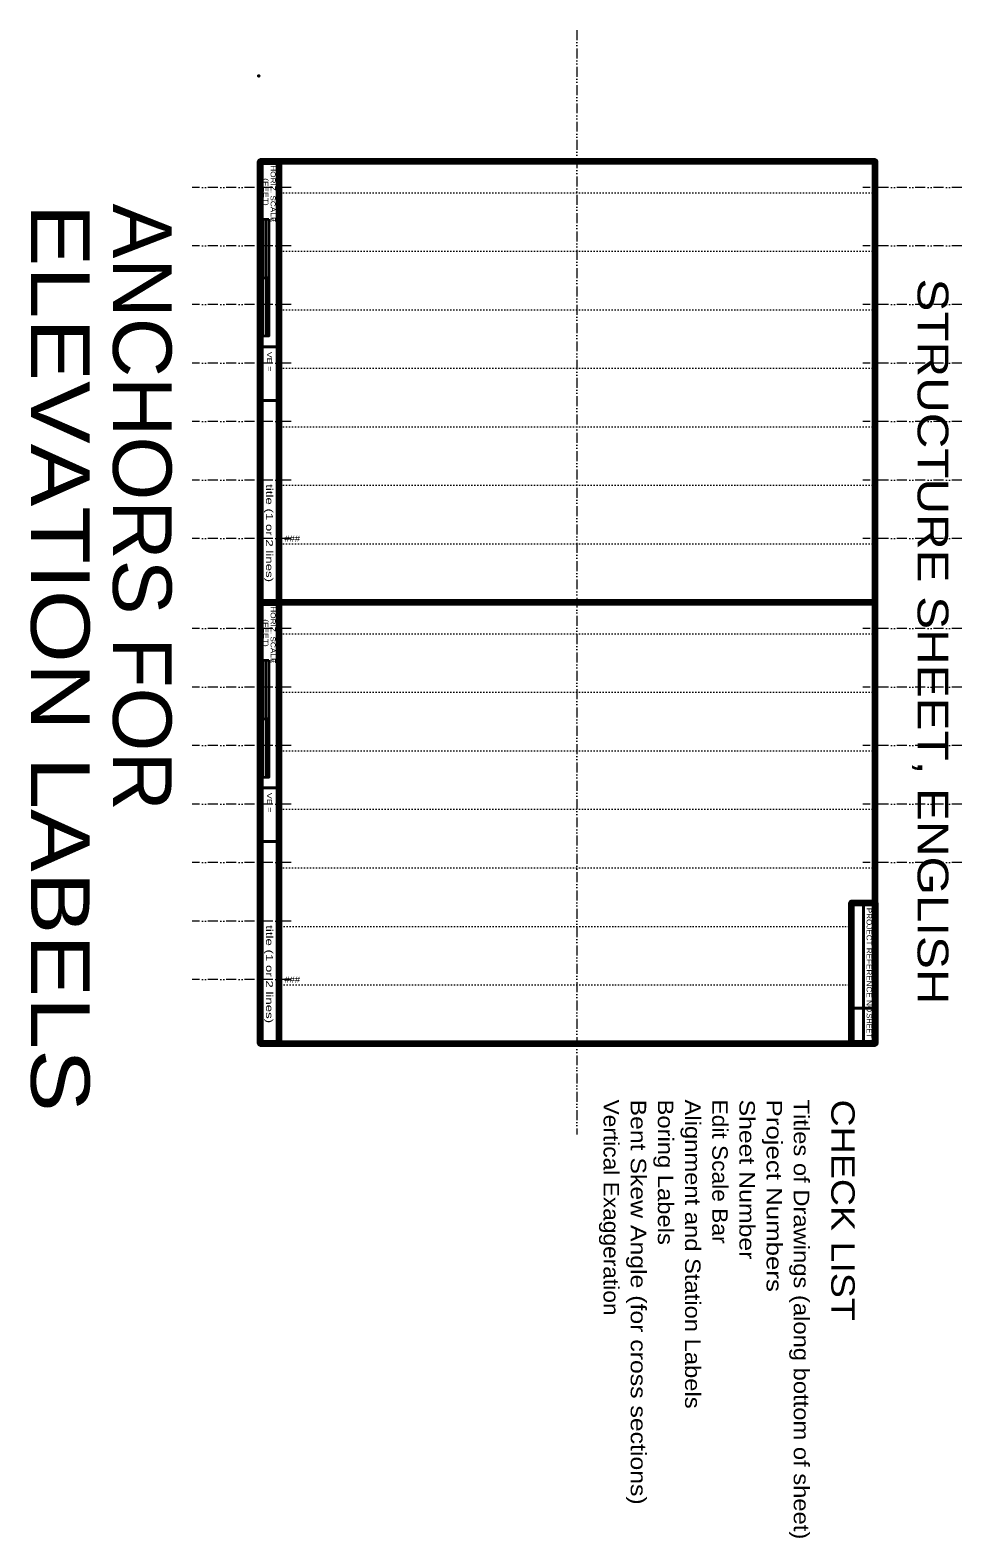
# Model space of a CAD drawing. Extents: x 278712 to 279914, y 171254 to 171792.
# Drawn here: x 279451 to 279610.1, y 171276.1 to 171533.7 of the extents above; entities that cross this region are included whole.
import ezdxf
from ezdxf.enums import TextEntityAlignment as Align

# ---------------------------------------------------------------- set-up
doc = ezdxf.new("R2010")
doc.units = 0
doc.header["$LTSCALE"] = 0.34
doc.header["$PDMODE"] = 32
doc.header["$PDSIZE"] = 0.17
doc.linetypes.add('DASH_DOUBLE_DOT', pattern=[9.2, 5, -1.2, 0.3, -1.2, 0.3, -1.2])
doc.linetypes.add('DOTTED', pattern=[1.5, 0.3, -1.2])
for name, color, linetype, lineweight in [('11', 7, 'DOTTED', 13), ('46', 7, 'DASH_DOUBLE_DOT', 13), ('60', 7, 'Continuous', 35), ('62', 7, 'Continuous', 35)]:
    doc.layers.add(name, color=color, linetype=linetype, lineweight=lineweight)
doc.layers.add('12', color=7, linetype='Continuous')

msp = doc.modelspace()

# ---------------------------------------------------------------- linework, layer by layer
at = {"layer": '11'}
for p, q in [((279595.3064, 171505.949), (279493.5061, 171505.949)), ((279595.3064, 171495.949), (279493.5061, 171495.949)), ((279595.3064, 171485.949), (279493.5061, 171485.949)), ((279595.3064, 171475.949), (279493.5061, 171475.949)), ((279595.3064, 171465.949), (279493.5061, 171465.949)), ((279595.3064, 171455.949), (279493.5061, 171455.949)), ((279595.3064, 171445.949), (279493.5061, 171445.949)), ((279595.3064, 171430.591), (279493.5061, 171430.591)), ((279595.3064, 171420.591), (279493.5061, 171420.591)), ((279595.3064, 171410.591), (279493.5061, 171410.591)), ((279595.3064, 171400.591), (279493.5061, 171400.591)), ((279595.3064, 171390.591), (279493.5061, 171390.591)), ((279591.3064, 171380.591), (279493.5061, 171380.591)), ((279591.3064, 171370.591), (279493.5061, 171370.591))]:
    msp.add_line(p, q, dxfattribs=at)
at = {"layer": '46'}
for p, q in [((279544.4064, 171533.7227), (279544.4064, 171345.0492)), ((279495.5874, 171506.8455), (279478.6921, 171506.8455)), ((279610.1204, 171506.8455), (279593.2251, 171506.8455)), ((279495.5874, 171496.8455), (279478.6921, 171496.8455)), ((279610.1204, 171496.8455), (279593.2251, 171496.8455)), ((279495.5874, 171486.8455), (279478.6921, 171486.8455)), ((279610.1204, 171486.8455), (279593.2251, 171486.8455)), ((279495.5874, 171476.8455), (279478.6921, 171476.8455)), ((279610.1204, 171476.8455), (279593.2251, 171476.8455)), ((279495.5874, 171466.8455), (279478.6921, 171466.8455)), ((279610.1204, 171466.8455), (279593.2251, 171466.8455)), ((279495.5874, 171456.8455), (279478.6921, 171456.8455)), ((279610.1204, 171456.8455), (279593.2251, 171456.8455)), ((279495.5874, 171446.8455), (279478.6921, 171446.8455)), ((279610.1204, 171446.8455), (279593.2251, 171446.8455)), ((279495.5874, 171431.4875), (279478.6921, 171431.4875)), ((279610.1204, 171431.4875), (279593.2251, 171431.4875)), ((279495.5874, 171421.4875), (279478.6921, 171421.4875)), ((279610.1204, 171421.4875), (279593.2251, 171421.4875)), ((279495.5874, 171411.4875), (279478.6921, 171411.4875)), ((279610.1204, 171411.4875), (279593.2251, 171411.4875)), ((279495.5874, 171401.4875), (279478.6921, 171401.4875)), ((279610.1204, 171401.4875), (279593.2251, 171401.4875)), ((279495.5874, 171391.4875), (279478.6921, 171391.4875)), ((279610.1204, 171391.4875), (279593.2251, 171391.4875)), ((279495.5874, 171381.4875), (279478.6921, 171381.4875)), ((279495.5874, 171371.4875), (279478.6921, 171371.4875))]:
    msp.add_line(p, q, dxfattribs=at)
at = {"layer": '60', "lineweight": 40}
for p, q in [((279493.5061, 171479.603), (279490.3061, 171479.6032)), ((279493.5061, 171470.4395), (279490.3061, 171470.4397)), ((279490.3061, 171459.949), (279490.3061, 171435.949)), ((279493.5061, 171404.245), (279490.3061, 171404.245)), ((279493.5061, 171395.0815), (279490.3061, 171395.0815)), ((279490.3061, 171384.591), (279490.3061, 171360.591)), ((279591.3064, 171384.591), (279591.3064, 171360.591)), ((279595.3064, 171384.591), (279591.3064, 171384.591)), ((279593.3064, 171384.591), (279593.3064, 171360.591)), ((279595.3064, 171366.591), (279591.3064, 171366.5912))]:
    msp.add_line(p, q, dxfattribs=at)
at = {"layer": '60', "lineweight": 90}
msp.add_line((279595.3064, 171435.949), (279490.3061, 171435.949), dxfattribs=at)
for points in [[(279493.5064, 171511.307), (279493.5061, 171435.949), (279490.3059, 171435.949), (279490.3061, 171511.307)], [(279490.3061, 171511.307), (279490.3061, 171360.591), (279595.3064, 171360.591), (279595.3064, 171511.307)], [(279493.5064, 171435.949), (279493.5061, 171360.591), (279490.3059, 171360.591), (279490.3061, 171435.949)], [(279595.3064, 171384.591), (279595.3064, 171360.591), (279591.3064, 171360.591), (279591.3064, 171384.591)]]:
    msp.add_lwpolyline(points, close=True, dxfattribs=at)
at = {"layer": '60'}
for points in [[(279491.8201, 171501.4097), (279491.8201, 171481.4097), (279490.8201, 171481.4097), (279490.8201, 171501.4097)], [(279491.8201, 171501.4097), (279491.8201, 171491.4097), (279491.3201, 171491.4097), (279491.3201, 171501.4097)], [(279491.3201, 171491.4097), (279491.3201, 171481.4097), (279490.8201, 171481.4097), (279490.8201, 171491.4097)], [(279491.8201, 171426.0517), (279491.8201, 171406.0517), (279490.8201, 171406.0517), (279490.8201, 171426.0517)], [(279491.8201, 171426.0517), (279491.8201, 171416.0517), (279491.3201, 171416.0517), (279491.3201, 171426.0517)], [(279491.3201, 171416.0517), (279491.3201, 171406.0517), (279490.8201, 171406.0517), (279490.8201, 171416.0517)]]:
    msp.add_lwpolyline(points, close=True, dxfattribs=at)
for p in [(279490.0884, 171525.9155), (279595.5241, 171360.4217)]:
    msp.add_point(p, dxfattribs=at)

# ---------------------------------------------------------------- texts
at = {"layer": '12', "width": 1.2}
for p in [(279495.7869, 171446.3455), (279495.7867, 171370.9875)]:
    msp.add_text('###', height=1, dxfattribs=at).set_placement(p, align=Align.CENTER)
at = {"layer": '60'}
for s, height, width, p in [('HORIZ. SCALE', 0.84, 1.25, (279492.1061, 171505.7641)), ('(FEET)', 0.84, 1.3, (279490.8661, 171506.0783)), ('0', 0.84, 0.9, (279492.2956, 171501.3732)), ('STRUCTURE SHEET, ENGLISH', 5.25, 1.2, (279602.5681, 171429.2638)), ('title (1 or 2 lines) ', 1.167, 1.45, (279491.3229, 171447.469)), ('HORIZ. SCALE', 0.84, 1.25, (279492.1061, 171430.4062)), ('(FEET)', 0.84, 1.3, (279490.8661, 171430.7203)), ('0', 0.84, 0.9, (279492.2956, 171426.0152)), ('PROJECT REFERENCE NO.', 0.9, 1.15, (279593.8564, 171374.6573)), ('title (1 or 2 lines) ', 1.167, 1.45, (279491.3229, 171372.1107))]:
    msp.add_text(s, height=height, rotation=270, dxfattribs=dict(at, width=width)).set_placement(p, align=Align.CENTER)
for s, height, width, p in [('VE =  ', 0.84, 1.35, (279491.4861, 171478.7572)), ('VE =  ', 0.84, 1.35, (279491.4861, 171403.399)), ('Vertical Exaggeration', 2.64, 1.1, (279548.9456, 171351.0007)), ('Bent Skew Angle (for cross sections)', 2.64, 1.2, (279553.5856, 171351.0007)), ('Boring Labels', 2.64, 1.15, (279558.2256, 171351.0007)), ('Alignment and Station Labels', 2.64, 1.15, (279562.8656, 171351.0007)), ('Edit Scale Bar', 2.64, 1.1, (279567.5056, 171351.0007)), ('Sheet Number', 2.64, 1.2, (279572.1456, 171351.0007)), ('Project Numbers', 2.64, 1.25, (279576.7856, 171351.0007)), ('Titles of Drawings (along bottom of sheet)', 2.64, 1.15, (279581.4256, 171351.0007)), ('CHECK LIST', 4, 1.2, (279587.8259, 171351.0007))]:
    msp.add_text(s, height=height, rotation=270, dxfattribs=dict(at, width=width)).set_placement(p)
msp.add_text('SHEET', height=0.9, rotation=270, dxfattribs=at).set_placement((279593.8564, 171363.6165), align=Align.CENTER)
at = {"layer": '62'}
for s, width, p in [('ELEVATION LABELS', 1.2, (279451.1911, 171504.0927)), ('ANCHORS FOR', 1.05, (279465.1911, 171504.0927))]:
    msp.add_text(s, height=10, rotation=270, dxfattribs=dict(at, width=width)).set_placement(p)

doc.saveas('drawing.dxf')
